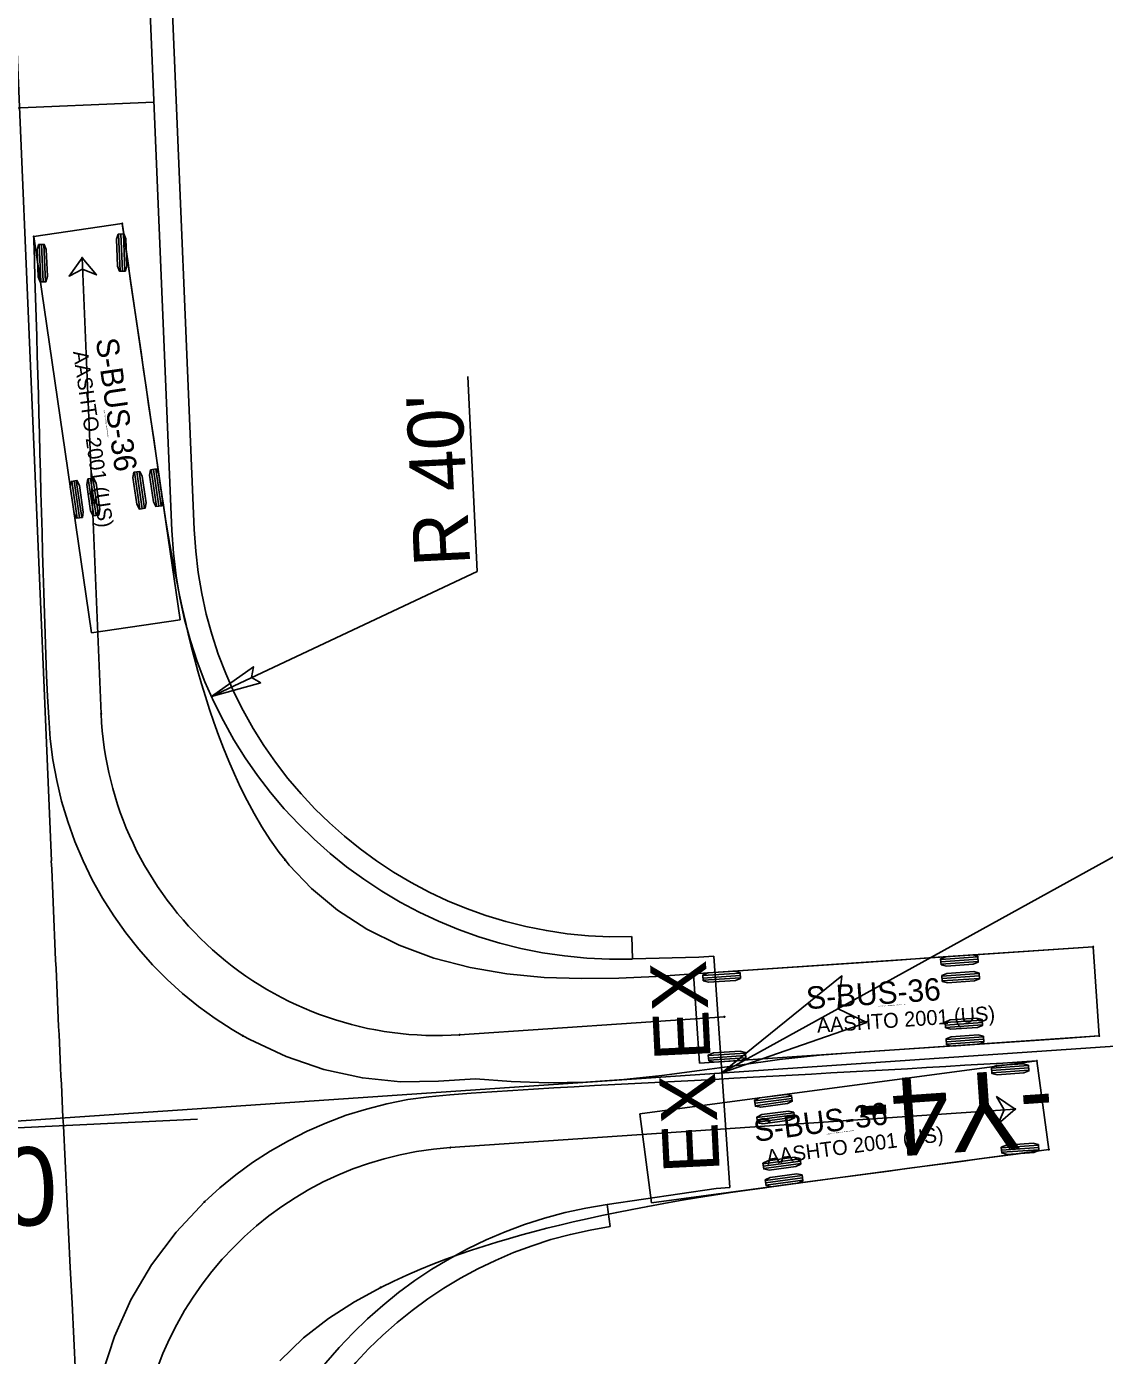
# Model space of a CAD drawing. Extents: x 2367848 to 2369479, y 800728 to 808616.
# Drawn here: x 2368846.5 to 2368942.8, y 803599.8 to 803718.6 of the extents above; entities that cross this region are included whole.
import ezdxf

# ---------------------------------------------------------------- set-up
doc = ezdxf.new("R2010")
doc.units = 0
for name, color, linetype in [('Prop AutoTurn Projected Path', 7, 'Continuous'), ('Prop AutoTurn Simulation', 7, 'Continuous'), ('Prop Conc 2ft 6in Curb and Gutter', 7, 'Continuous'), ('Prop Dimension', 7, 'Continuous'), ('Prop EOT', 7, 'Continuous'), ('Prop Horizontal Alignment', 7, 'Continuous'), ('Prop Horizontal Alignment Station Label', 7, 'Continuous'), ('Prop Lane Lines', 7, 'Continuous'), ('Prop Superelevation Label', 7, 'Continuous'), ('Prop Terminator CELL', 7, 'Continuous')]:
    doc.layers.add(name, color=color, linetype=linetype)

msp = doc.modelspace()

# ---------------------------------------------------------------- linework, layer by layer
at = {"layer": 'Prop AutoTurn Projected Path'}
for p, q in [((2368853.21, 803657.14), (2368851.5, 803697.91)), ((2368885.22, 803628.47), (2368908.88, 803630.08)), ((2368884.4, 803618.39), (2368934.86, 803621.83))]:
    msp.add_line(p, q, dxfattribs=at)
for centre, start, end in [((2368883.18, 803658.4), 182.4089, 273.9006), ((2368886.44, 803588.46), 93.9006, 182.8037)]:
    msp.add_arc(centre, 30, start, end, dxfattribs=at)
at = {"layer": 'Prop AutoTurn Simulation'}
for p, q in [((2368855.09, 803700.97), (2368847.18, 803699.81)), ((2368854.77, 803700.04), (2368854.9, 803696.71)), ((2368854.98, 803700.05), (2368855.11, 803696.72)), ((2368860.27, 803665.54), (2368855.09, 803700.97)), ((2368855.19, 803700.06), (2368855.32, 803696.73)), ((2368847.18, 803699.81), (2368852.35, 803664.39)), ((2368847.18, 803699.81), (2368847.18, 803699.81)), ((2368847.66, 803699.09), (2368847.81, 803695.76)), ((2368847.87, 803699.1), (2368848.02, 803695.77)), ((2368848.08, 803699.11), (2368848.23, 803695.78)), ((2368856.19, 803678.76), (2368856.67, 803675.46)), ((2368856.39, 803678.79), (2368856.88, 803675.49)), ((2368856.6, 803678.82), (2368857.08, 803675.52)), ((2368857.67, 803678.97), (2368858.15, 803675.68)), ((2368857.88, 803679), (2368858.36, 803675.71)), ((2368858.08, 803679.03), (2368858.57, 803675.74)), ((2368850.58, 803677.94), (2368851.06, 803674.64)), ((2368850.79, 803677.97), (2368851.27, 803674.67)), ((2368850.99, 803678), (2368851.47, 803674.7)), ((2368852.06, 803678.16), (2368852.55, 803674.86)), ((2368852.27, 803678.19), (2368852.75, 803674.89)), ((2368852.48, 803678.22), (2368852.96, 803674.92)), ((2368852.35, 803664.39), (2368860.27, 803665.54)), ((2368941.83, 803636.34), (2368906.11, 803633.9)), ((2368942.37, 803628.36), (2368941.83, 803636.34)), ((2368928.21, 803635.2), (2368931.53, 803635.43)), ((2368928.22, 803634.99), (2368931.55, 803635.22)), ((2368928.24, 803634.78), (2368931.56, 803635.01)), ((2368906.11, 803633.9), (2368906.66, 803625.92)), ((2368906.96, 803633.75), (2368910.28, 803633.98)), ((2368906.97, 803633.54), (2368910.3, 803633.77)), ((2368906.98, 803633.34), (2368910.31, 803633.56)), ((2368928.31, 803633.7), (2368931.63, 803633.93)), ((2368928.32, 803633.5), (2368931.65, 803633.72)), ((2368928.34, 803633.29), (2368931.66, 803633.51)), ((2368928.59, 803629.55), (2368931.92, 803629.77)), ((2368928.61, 803629.34), (2368931.93, 803629.57)), ((2368928.62, 803629.13), (2368931.95, 803629.36)), ((2368906.66, 803625.92), (2368942.37, 803628.36)), ((2368928.69, 803628.05), (2368932.02, 803628.28)), ((2368928.71, 803627.84), (2368932.03, 803628.07)), ((2368928.72, 803627.63), (2368932.05, 803627.86)), ((2368907.44, 803626.6), (2368910.77, 803626.83)), ((2368907.46, 803626.39), (2368910.78, 803626.62)), ((2368907.47, 803626.19), (2368910.8, 803626.41)), ((2368936.8, 803626.13), (2368901.32, 803621.39)), ((2368906.66, 803625.92), (2368906.66, 803625.92)), ((2368936.06, 803625.71), (2368932.73, 803625.48)), ((2368936.07, 803625.5), (2368932.74, 803625.27)), ((2368936.08, 803625.29), (2368932.76, 803625.06)), ((2368937.86, 803618.2), (2368936.8, 803626.13)), ((2368936.8, 803626.13), (2368936.8, 803626.13)), ((2368914.89, 803622.99), (2368911.59, 803622.55)), ((2368914.92, 803622.78), (2368911.62, 803622.34)), ((2368914.95, 803622.58), (2368911.64, 803622.13)), ((2368901.32, 803621.39), (2368902.38, 803613.46)), ((2368915.09, 803621.5), (2368911.79, 803621.06)), ((2368915.12, 803621.3), (2368911.81, 803620.85)), ((2368915.15, 803621.09), (2368911.84, 803620.65)), ((2368902.38, 803613.46), (2368937.86, 803618.2)), ((2368936.95, 803618.6), (2368933.63, 803618.37)), ((2368936.97, 803618.39), (2368933.64, 803618.16)), ((2368936.98, 803618.18), (2368933.65, 803617.96)), ((2368915.64, 803617.37), (2368912.34, 803616.93)), ((2368915.67, 803617.17), (2368912.37, 803616.72)), ((2368915.7, 803616.96), (2368912.39, 803616.52)), ((2368915.84, 803615.89), (2368912.54, 803615.44)), ((2368915.87, 803615.68), (2368912.56, 803615.24)), ((2368915.9, 803615.47), (2368912.59, 803615.03))]:
    msp.add_line(p, q, dxfattribs=at)
for points in [[(2368854.72, 803700.04), (2368855.24, 803700.06), (2368855.41, 803699.6), (2368855.51, 803697.21), (2368855.37, 803696.73), (2368854.85, 803696.71), (2368854.68, 803697.17), (2368854.58, 803699.57)], [(2368847.61, 803699.09), (2368848.13, 803699.11), (2368848.31, 803698.65), (2368848.41, 803696.26), (2368848.28, 803695.78), (2368847.76, 803695.76), (2368847.58, 803696.22), (2368847.48, 803698.62)], [(2368851.5, 803697.91), (2368850.35, 803696.28), (2368851.54, 803696.91), (2368852.78, 803696.38)], [(2368856.14, 803678.75), (2368856.65, 803678.82), (2368856.87, 803678.39), (2368857.22, 803676.01), (2368857.13, 803675.53), (2368856.62, 803675.45), (2368856.4, 803675.89), (2368856.05, 803678.27)], [(2368857.62, 803678.97), (2368858.14, 803679.04), (2368858.36, 803678.6), (2368858.7, 803676.23), (2368858.62, 803675.74), (2368858.1, 803675.67), (2368857.88, 803676.11), (2368857.53, 803678.48)], [(2368850.53, 803677.93), (2368851.04, 803678.01), (2368851.27, 803677.57), (2368851.61, 803675.19), (2368851.53, 803674.71), (2368851.01, 803674.63), (2368850.79, 803675.07), (2368850.44, 803677.45)], [(2368852.01, 803678.15), (2368852.53, 803678.22), (2368852.75, 803677.78), (2368853.1, 803675.41), (2368853.01, 803674.92), (2368852.5, 803674.85), (2368852.27, 803675.29), (2368851.93, 803677.66)], [(2368928.24, 803634.73), (2368928.2, 803635.25), (2368928.66, 803635.44), (2368931.05, 803635.6), (2368931.53, 803635.48), (2368931.56, 803634.96), (2368931.11, 803634.77), (2368928.72, 803634.61)], [(2368906.99, 803633.28), (2368906.95, 803633.8), (2368907.41, 803633.99), (2368909.8, 803634.15), (2368910.28, 803634.03), (2368910.31, 803633.51), (2368909.86, 803633.32), (2368907.46, 803633.16)], [(2368928.34, 803633.24), (2368928.31, 803633.76), (2368928.76, 803633.94), (2368931.16, 803634.11), (2368931.63, 803633.98), (2368931.67, 803633.46), (2368931.21, 803633.28), (2368928.82, 803633.11)], [(2368928.62, 803629.08), (2368928.59, 803629.6), (2368929.04, 803629.79), (2368931.44, 803629.95), (2368931.91, 803629.83), (2368931.95, 803629.31), (2368931.5, 803629.12), (2368929.1, 803628.96)], [(2368928.73, 803627.58), (2368928.69, 803628.1), (2368929.15, 803628.29), (2368931.54, 803628.45), (2368932.02, 803628.33), (2368932.05, 803627.81), (2368931.6, 803627.62), (2368929.2, 803627.46)], [(2368907.48, 803626.13), (2368907.44, 803626.65), (2368907.9, 803626.84), (2368910.29, 803627), (2368910.77, 803626.88), (2368910.8, 803626.36), (2368910.35, 803626.17), (2368907.95, 803626.01)], [(2368936.05, 803625.76), (2368936.09, 803625.24), (2368935.63, 803625.05), (2368933.24, 803624.89), (2368932.76, 803625.01), (2368932.73, 803625.53), (2368933.18, 803625.72), (2368935.58, 803625.88)], [(2368914.89, 803623.04), (2368914.95, 803622.52), (2368914.51, 803622.31), (2368912.13, 803621.99), (2368911.65, 803622.08), (2368911.58, 803622.6), (2368912.02, 803622.82), (2368914.4, 803623.13)], [(2368934.86, 803621.83), (2368933.19, 803622.94), (2368933.86, 803621.76), (2368933.35, 803620.51)], [(2368915.08, 803621.55), (2368915.15, 803621.04), (2368914.71, 803620.82), (2368912.33, 803620.5), (2368911.85, 803620.6), (2368911.78, 803621.11), (2368912.22, 803621.33), (2368914.6, 803621.65)], [(2368936.95, 803618.65), (2368936.98, 803618.13), (2368936.53, 803617.94), (2368934.13, 803617.78), (2368933.66, 803617.9), (2368933.62, 803618.42), (2368934.08, 803618.61), (2368936.47, 803618.77)], [(2368915.64, 803617.42), (2368915.7, 803616.91), (2368915.26, 803616.69), (2368912.88, 803616.37), (2368912.4, 803616.47), (2368912.33, 803616.98), (2368912.77, 803617.2), (2368915.15, 803617.52)], [(2368915.83, 803615.94), (2368915.9, 803615.42), (2368915.46, 803615.2), (2368913.08, 803614.89), (2368912.6, 803614.98), (2368912.53, 803615.5), (2368912.97, 803615.71), (2368915.35, 803616.03)]]:
    msp.add_lwpolyline(points, close=True, dxfattribs=at)
for points in [[(2368869.64, 803644.09), (2368869.12, 803644.76), (2368868.31, 803645.9), (2368867.57, 803647.06), (2368866.88, 803648.23), (2368866.25, 803649.4), (2368865.66, 803650.57), (2368865.12, 803651.75), (2368864.61, 803652.92), (2368864.13, 803654.09), (2368863.69, 803655.25), (2368863.28, 803656.4), (2368862.89, 803657.55), (2368862.52, 803658.7), (2368862.18, 803659.83), (2368861.85, 803660.96), (2368861.55, 803662.09), (2368861.26, 803663.2), (2368860.99, 803664.31), (2368860.73, 803665.41), (2368860.47, 803666.55), (2368860.22, 803667.75), (2368859.96, 803668.99), (2368859.71, 803670.28), (2368859.47, 803671.61), (2368859.23, 803672.98), (2368859, 803674.38), (2368858.77, 803675.8), (2368858.55, 803677.25), (2368858.34, 803678.73), (2368858.12, 803680.22), (2368857.9, 803681.73), (2368857.68, 803683.25), (2368857.45, 803684.79), (2368857.23, 803686.34), (2368857, 803687.9), (2368856.77, 803689.47), (2368856.54, 803691.05), (2368856.31, 803692.63), (2368856.08, 803694.22), (2368855.84, 803695.82), (2368855.61, 803697.42), (2368855.37, 803699.03), (2368855.14, 803700.64), (2368855.09, 803700.97)], [(2368865.85, 803628.38), (2368864.91, 803628.93), (2368863.38, 803629.92), (2368861.9, 803631), (2368860.47, 803632.16), (2368859.1, 803633.4), (2368857.8, 803634.72), (2368856.57, 803636.11), (2368855.41, 803637.57), (2368854.33, 803639.1), (2368853.33, 803640.68), (2368852.42, 803642.32), (2368851.59, 803644.01), (2368850.86, 803645.75), (2368850.22, 803647.53), (2368849.68, 803649.34), (2368849.24, 803651.18), (2368848.9, 803653.04), (2368848.66, 803654.93), (2368848.52, 803656.82), (2368848.43, 803658.71), (2368848.34, 803660.58), (2368848.27, 803662.44), (2368848.2, 803664.29), (2368848.14, 803666.13), (2368848.08, 803667.96), (2368848.03, 803669.77), (2368847.97, 803671.58), (2368847.93, 803673.37), (2368847.88, 803675.16), (2368847.83, 803676.93), (2368847.78, 803678.7), (2368847.74, 803680.46), (2368847.69, 803682.21), (2368847.64, 803683.96), (2368847.6, 803685.7), (2368847.55, 803687.44), (2368847.5, 803689.17), (2368847.45, 803690.9), (2368847.4, 803692.62), (2368847.35, 803694.34), (2368847.29, 803696.05), (2368847.24, 803697.76), (2368847.19, 803699.47), (2368847.18, 803699.81)], [(2368941.83, 803636.34), (2368938.26, 803636.09), (2368934.68, 803635.85), (2368931.11, 803635.61), (2368927.54, 803635.36), (2368923.97, 803635.12), (2368920.4, 803634.88), (2368916.83, 803634.63), (2368913.25, 803634.39), (2368909.68, 803634.15), (2368906.11, 803633.9), (2368906.11, 803633.9), (2368906.11, 803633.9), (2368902.78, 803633.69), (2368899.44, 803633.53), (2368896.11, 803633.49), (2368892.77, 803633.6), (2368889.45, 803633.91), (2368886.16, 803634.48), (2368882.93, 803635.32), (2368879.83, 803636.47), (2368876.94, 803637.9), (2368874.32, 803639.6), (2368872, 803641.53), (2368870, 803643.64), (2368869.64, 803644.09)], [(2368942.37, 803628.36), (2368938.8, 803628.11), (2368935.23, 803627.87), (2368931.66, 803627.63), (2368928.09, 803627.38), (2368924.51, 803627.14), (2368920.94, 803626.9), (2368917.37, 803626.64), (2368913.81, 803626.25), (2368910.24, 803625.74), (2368906.66, 803625.26), (2368906.66, 803625.26), (2368903.3, 803624.82), (2368899.91, 803624.46), (2368896.51, 803624.24), (2368893.13, 803624.18), (2368889.83, 803624.29), (2368886.66, 803624.54), (2368883.34, 803624.33), (2368879.96, 803624.27), (2368876.54, 803624.61), (2368873.11, 803625.36), (2368869.75, 803626.51), (2368866.49, 803628.03), (2368865.85, 803628.38)], [(2368862.43, 803613.53), (2368863.8, 803614.78), (2368865.24, 803615.95), (2368866.74, 803617.05), (2368868.31, 803618.07), (2368869.94, 803619), (2368871.61, 803619.85), (2368873.34, 803620.61), (2368875.1, 803621.27), (2368876.9, 803621.83), (2368878.74, 803622.3), (2368880.6, 803622.67), (2368882.47, 803622.93), (2368884.36, 803623.1), (2368886.25, 803623.24), (2368888.11, 803623.37), (2368889.97, 803623.49), (2368891.82, 803623.61), (2368893.65, 803623.72), (2368895.47, 803623.82), (2368897.29, 803623.92), (2368899.09, 803624.02), (2368900.88, 803624.11), (2368902.66, 803624.21), (2368904.43, 803624.3), (2368906.2, 803624.39), (2368907.96, 803624.48), (2368909.71, 803624.58), (2368911.46, 803624.67), (2368913.2, 803624.76), (2368914.93, 803624.86), (2368916.66, 803624.95), (2368918.38, 803625.05), (2368920.11, 803625.14), (2368921.82, 803625.24), (2368923.54, 803625.34), (2368925.25, 803625.43), (2368926.95, 803625.53), (2368928.66, 803625.63), (2368930.36, 803625.74), (2368932.06, 803625.84), (2368933.75, 803625.94), (2368935.45, 803626.04), (2368936.8, 803626.13)], [(2368878.18, 803605.88), (2368879.35, 803606.45), (2368880.52, 803606.99), (2368881.69, 803607.49), (2368882.85, 803607.96), (2368884, 803608.4), (2368885.15, 803608.82), (2368886.3, 803609.21), (2368887.43, 803609.58), (2368888.56, 803609.94), (2368889.68, 803610.27), (2368890.8, 803610.58), (2368891.91, 803610.88), (2368893.01, 803611.17), (2368894.17, 803611.46), (2368895.37, 803611.74), (2368896.63, 803612.03), (2368897.93, 803612.31), (2368899.26, 803612.59), (2368900.64, 803612.86), (2368902.04, 803613.13), (2368903.47, 803613.39), (2368904.93, 803613.64), (2368906.4, 803613.89), (2368907.9, 803614.13), (2368909.42, 803614.36), (2368910.95, 803614.58), (2368912.49, 803614.8), (2368914.05, 803615.02), (2368915.62, 803615.22), (2368917.19, 803615.44), (2368918.78, 803615.65), (2368920.37, 803615.86), (2368921.97, 803616.07), (2368923.57, 803616.29), (2368925.18, 803616.5), (2368926.8, 803616.72), (2368928.41, 803616.93), (2368930.04, 803617.15), (2368931.66, 803617.37), (2368933.29, 803617.59), (2368934.92, 803617.8), (2368936.55, 803618.02), (2368937.86, 803618.2)], [(2368853.31, 803598.14), (2368854.4, 803601.5), (2368855.87, 803604.77), (2368857.72, 803607.9), (2368859.91, 803610.83), (2368862.43, 803613.53)], [(2368869.17, 803599.31), (2368871.27, 803601.37), (2368873.52, 803603.11), (2368875.83, 803604.6), (2368878.18, 803605.88)]]:
    msp.add_lwpolyline(points, dxfattribs=at)
for centre in [(2368855.09, 803700.97), (2368847.18, 803699.81), (2368851.5, 803697.91), (2368853.21, 803657.14), (2368853.21, 803657.14), (2368869.64, 803644.09), (2368869.64, 803644.09), (2368941.83, 803636.34), (2368908.88, 803630.08), (2368865.85, 803628.38), (2368865.85, 803628.38), (2368885.22, 803628.47), (2368885.22, 803628.47), (2368942.37, 803628.36), (2368936.8, 803626.13), (2368934.86, 803621.83), (2368884.4, 803618.39), (2368884.4, 803618.39), (2368937.86, 803618.2), (2368862.43, 803613.53), (2368862.43, 803613.53), (2368878.18, 803605.88), (2368878.18, 803605.88)]:
    msp.add_circle(centre, 0.0417, dxfattribs=at)
at = {"layer": 'Prop Conc 2ft 6in Curb and Gutter'}
for p, q in [((2368861.52, 803673.62), (2368858.91, 803735.87)), ((2368900.66, 803635.24), (2368900.6, 803637.24)), ((2368898.4, 803613.3), (2368898.69, 803611.32))]:
    msp.add_line(p, q, dxfattribs=at)
for centre, start, end in [((2368899.49, 803675.22), 182.4089, 271.6689), ((2368904.18, 803573.72), 98.3031, 182.8066)]:
    msp.add_arc(centre, 38, start, end, dxfattribs=at)
at = {"layer": 'Prop Dimension'}
for p, q in [((2368886.8, 803669.86), (2368885.95, 803687.3)), ((2368908.66, 803625.06), (2369016.92, 803684.91)), ((2368863.06, 803658.71), (2368886.8, 803669.86))]:
    msp.add_line(p, q, dxfattribs=at)
at = {"layer": 'Prop EOT'}
for p, q in [((2368859.53, 803673.54), (2368856.91, 803735.78)), ((2368900.66, 803635.24), (2368906.59, 803635.41)), ((2368906.59, 803635.41), (2368907.95, 803635.48)), ((2368907.95, 803635.48), (2368909.36, 803614.82)), ((2368908.16, 803614.72), (2368898.4, 803613.3)), ((2368909.36, 803614.82), (2368908.16, 803614.72))]:
    msp.add_line(p, q, dxfattribs=at)
for centre, start, end in [((2368899.49, 803675.22), 182.4089, 271.6689), ((2368904.18, 803573.72), 98.3031, 182.8066)]:
    msp.add_arc(centre, 40, start, end, dxfattribs=at)
at = {"layer": 'Prop Horizontal Alignment'}
msp.add_line((2368843.81, 803620.63), (2369108.85, 803638.71), dxfattribs=at)
msp.add_arc((2677047.33, 818679.94), 308571.21, 182.7974457, 182.8728926, dxfattribs=at)
at = {"layer": 'Prop Lane Lines'}
msp.add_line((2368848.76, 803644.01), (2368844.92, 803735.28), dxfattribs=at)
for centre, radius, start, end in [((2372339.67, 803790.87), 3494, 182.40885, 182.79745), ((2677047.33, 818679.94), 308565.21, 182.7974457, 182.8728926), ((2677047.33, 818679.94), 308577.21, 182.7974457, 182.8728926)]:
    msp.add_arc(centre, radius, start, end, dxfattribs=at)
at = {"layer": 'Prop Superelevation Label'}
for p, q in [((2368821.95, 803710.3), (2368857.92, 803711.81)), ((2368825.86, 803619.17), (2368861.82, 803620.93))]:
    msp.add_line(p, q, dxfattribs=at)
at = {"layer": 'Prop Terminator CELL'}
for points in [[(2368867.46, 803659.92), (2368863.06, 803658.71), (2368866.81, 803661.36), (2368866.63, 803660.39)], [(2368921.6, 803629.55), (2368908.66, 803625.06), (2368919.38, 803633.72), (2368919.03, 803630.79)]]:
    msp.add_lwpolyline(points, close=True, dxfattribs=at)

# ---------------------------------------------------------------- texts
at = {"layer": 'Prop AutoTurn Simulation'}
for s, height, rotation, p in [('S-BUS-36', 2, 278.3087, (2368852.72, 803690.61)), ('AASHTO 2001 (US)', 1.3333, 278.3087, (2368850.69, 803689.52)), ('(c) 2014 Transoft Solutions, Inc. All rights reserved.', 0.08, 278.3087, (2368853.45, 803684.28)), ('S-BUS-36', 2, 3.9006, (2368916.25, 803630.75)), ('AASHTO 2001 (US)', 1.3333, 3.9006, (2368917.18, 803628.64)), ('(c) 2014 Transoft Solutions, Inc. All rights reserved.', 0.08, 3.9006, (2368922.62, 803630.98)), ('S-BUS-36', 2, 7.6077, (2368911.64, 803618.89)), ('AASHTO 2001 (US)', 1.3333, 7.6077, (2368912.71, 803616.85)), ('(c) 2014 Transoft Solutions, Inc. All rights reserved.', 0.08, 7.6077, (2368917.98, 803619.54))]:
    msp.add_text(s, height=height, rotation=rotation, dxfattribs=at).set_placement(p)
at = {"layer": 'Prop Dimension'}
for s, p in [("R 40'", (2368886.18, 803670.45)), ('EX', (2368907.66, 803626.28)), ('EX', (2368908.47, 803616.23))]:
    msp.add_text(s, height=5, rotation=92.7929, dxfattribs=at).set_placement(p)
at = {"layer": 'Prop Horizontal Alignment Station Label'}
msp.add_text('-Y4-', height=7, rotation=183.9006, dxfattribs=at).set_placement((2368938.1, 803625.54))
at = {"layer": 'Prop Superelevation Label'}
msp.add_text('025', height=7, rotation=182.4693, dxfattribs=at).set_placement((2368849.14, 803618.53))

doc.saveas('drawing.dxf')
